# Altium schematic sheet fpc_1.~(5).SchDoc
size A; SheetNumber: 1; SheetTotal: 1
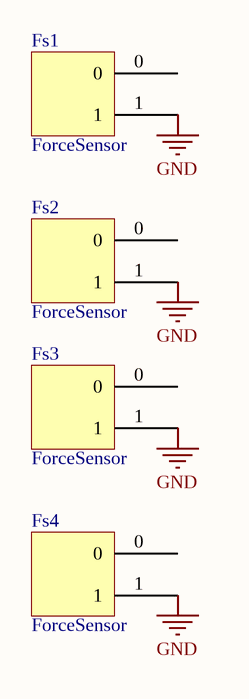
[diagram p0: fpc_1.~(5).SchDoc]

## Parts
Fs1  ForceSensor  [sensor_connector]
Fs2  ForceSensor  [sensor_connector]
Fs3  ForceSensor  [sensor_connector]
Fs4  ForceSensor  [sensor_connector]

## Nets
GND: Fs1.1 Fs2.1 Fs3.1 Fs4.1

Not connected (* = marked no-connect by the designer): Fs1 0; Fs2 0; Fs3 0; Fs4 0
